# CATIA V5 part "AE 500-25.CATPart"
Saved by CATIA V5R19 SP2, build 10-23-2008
Part number: AE 500-25
Bounding box of the stored display mesh (mm): x -22.494 to 22.494, y -22.494 to 22.494, z 0 to 100
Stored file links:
  C:\Users\Bora\Desktop\3D Katı model\AE serisi\AE 500\AE 500-25.CATPart
  C:\Program Files\Dassault Systemes\B19\intel_a\reffiles\standard\MetricThickPitch.txt
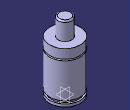
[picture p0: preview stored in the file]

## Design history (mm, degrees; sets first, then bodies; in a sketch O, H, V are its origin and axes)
Body1 (main body)
  Sketch1 on yz-plane, origin (0, 0, 0), H (0, 1, 0), V (0, 0, 1)
    point P1 (22.5, 58.5)
    point P8 (22.5, 60.5)
    point P9 (22.5, 60.5)
    point P10 (22.5, 58.5)
    point P11 (10, 98)
    point P13 (10, 98)
    line L1 (22.5, 58.5) -> (22.5, 8)
    line L2 (22.5, 4) -> (22.5, 0)
    line L3 (20, 8) -> (20, 4)
    line L4 (22.5, 74) -> (22.5, 60.5)
    arc A1 centre (22.5, 59.5) radius 1 from (22.5, 60.5) to (22.5, 58.5) ccw
    line L5 (10, 98) -> (10, 74)
    arc A2 centre (8, 98) radius 2 from (10, 98) to (8, 100) ccw
    line L6 (8, 100) -> (0, 100)
    point P15 (0, 100)
    line L7 (10, 74) -> (22.5, 74)
    line L8 (0, 0) -> (22.5, 0)
    line L9 (20, 8) -> (22.5, 8)
    line L10 (20, 4) -> (22.5, 4)
    coincidence: P15 V, P1 P10, P8 P9, P11 P13
    tangency: L6 A2
    horizontal: L7 H, L8 H, L9 H, L10 H
  Shaft1: profile Sketch1, axis Sketch1.V, angle 360
  Sketch2 on face of Shaft1 from Sketch1.L8, origin (0, 0, 0), H (1, 0, 0), V (0, -1, 0)
    point P1 (10, 0)
    distance P1 V = 10
  Hole1: placed by Sketch2, at (10, 0, 0) direction (0, 0, 1), diameter 6.647, depth 13, threaded "M8", thread diameter 8, thread depth 13, pitch 1.25
  CircPattern1: of Hole1, instances 2, angular step 180, axis from xy-plane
